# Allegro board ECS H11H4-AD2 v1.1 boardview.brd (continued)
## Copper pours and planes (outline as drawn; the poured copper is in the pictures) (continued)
GND on PWR (solid shape): outline of 10788 points within 117.45,130.68 192.89,199.01
GND on PWR (solid shape): outline of 19119 points within 73.76,77.22 183.87,203.58
GND on GND (solid shape): outline of 132067 points within 0.51,0.51 199.49,243.33
+ATX_3VSB on TOP (solid shape): 165.79,58.24 165.79,54.03 165.38,53.62 162.17,53.62 161.86,53.51 161.72,53.21 161.72,53.19 161.67,53.14 161.67,52.2 161.34,51.87 159.31,51.87 159.27,51.88 159.26,51.92 159.26,53.42 159.26,53.57 159.11,53.72 159.11,55.63 158.6,56.13 155.63,56.13 155.59,56.15 155.58,56.18 155.58,56.36 154.15,57.78 154.15,58.4 154.53,58.78 165.25,58.78
+ATX_3VSB on BOTTOM (solid shape): outline of 112 points within 29.29,48.98 57.76,57
+ATX_5VSB on TOP (solid shape): 6.88,154.94 6.92,154.93 6.93,154.89 6.93,153.33 7.49,153.33 7.49,154.89 7.51,154.93 7.54,154.94 10.13,154.94 10.52,154.56 10.52,153.29 9.75,152.53 9.75,150.75 9.63,150.62 9.25,150.62 8.61,151.26 5.82,151.26 5.56,151.51 5.56,152.53 6.2,153.16 6.2,153.31 6.22,153.33 6.22,154.89 6.24,154.93 6.27,154.94
+ATX_5VSB on TOP (solid shape): outline of 127 points within 146.66,42.55 165.67,51.69
+DDR_VTT on TOP (solid shape): 56.49,88.29 56.49,87.73 56.16,87.4 56.16,84.96 56.47,84.65 56.47,84.25 56.47,83.86 56.16,83.54 56.16,81.14 57.16,80.14 59.53,80.14 60.32,80.92 95.91,80.92 96.06,80.77 96.06,79.81 95.91,79.65 60.84,79.65 60.05,78.87 56.63,78.87 54.89,80.61 54.89,88.57 55.02,88.7 56.08,88.7
+DDR_VTT on TOP (solid shape): 144.69,70.15 144.73,70.14 144.74,70.1 144.74,69.92 144.85,69.81 144.86,69.79 144.86,69.77 145.41,69.28 145.61,69.99 145.59,70.09 145.69,70.15 145.93,70.15 146,70.08 146.01,70.06 146.01,70.03 146.4,69.42 146.81,70.01 146.81,70.11 146.9,70.15 148.23,70.15 149.02,69.37 149.02,67.69 148.77,67.44 145.62,67.44 145.31,67.74 145.31,68.33 144.5,69.14 144.5,70.1 144.55,70.15
+DDR_VTT on BOTTOM (solid shape): 121.01,70.89 141.74,70.89 143.39,69.24 146.65,69.24 147.56,70.15 148.11,70.15 148.64,69.62 148.64,68.96 147.65,67.97 142.87,67.97 141.21,69.62 120.24,69.62 110.21,79.65 94.82,79.65 94.64,79.83 94.64,80.8 94.77,80.92 95.35,80.92 95.4,80.92 110.97,80.92
+DRIVER_POWER on TOP (solid shape): 197.87,130.1 197.87,126.82 197.61,126.57 194.97,126.57 194.82,126.72 194.82,128.32 194.41,128.73 191.47,128.73 191.36,128.83 191.36,130.23 191.49,130.35 197.61,130.35
+DVI_VGA_VCC on TOP (solid shape): 164.01,232.89 164.01,231.9 164.31,231.6 164.31,231.53 164.3,231.5 164.26,231.48 163.92,231.48 163.79,231.36 163.23,231.36 161.42,229.54 161.42,227.53 161.01,227.13 157,227.13 156.82,227.3 156.82,229.26 160.78,233.22 163.68,233.22
+R_VDD10 on TOP (solid shape): 58.84,195.8 58.84,194.98 58.85,194.97 58.85,194.74 60.2,193.4 60.2,192.61 59.99,192.41 55.73,192.41 55.58,192.56 55.58,195.81 55.83,196.06 58.57,196.06
+R_VDD33 on TOP (solid shape): 55.3,193.22 55.3,191.13 57,189.43 57,186.74 55.93,185.67 55.02,185.67 54.74,185.95 54.74,190.4 54.51,190.63 53.92,190.63 53.7,190.86 53.7,192.32 53.7,192.51 53.72,192.53 53.72,193.29 53.9,193.47 55.04,193.47
+R_VDDREG on TOP (solid shape): 52.86,199.87 52.86,199.24 53.42,198.68 53.42,198.15 53.68,197.88 53.68,193.7 53.42,193.43 53.42,192.48 53.21,192.28 52.25,192.28 52.02,192.51 52.02,195.84 52.03,195.88 52.07,195.89 52.48,196.32 52.07,196.75 52.03,196.77 52.02,196.81 52.02,197.87 52.68,198.53 52.68,199.87 52.73,199.92 52.81,199.92
+USB3VCC2_2 on TOP (solid shape): outline of 92 points within 4.29,47.57 10.64,63.63
+USB3VCC_C1 on TOP (solid shape): 107.65,233.68 110.67,233.68 111.38,232.97 111.38,224.69 111,224.31 107.98,224.31 105.16,221.49 105.16,220.57 106.58,219.15 107.37,219.15 108.43,218.08 108.43,218.06 109.63,216.87 109.63,214 109.35,213.72 107.67,213.72 107.44,213.94 107.44,213.97 107.34,214.07 107.34,214.91 102.21,220.04 102.21,222.53 106.58,226.9 107.65,226.9 109.7,228.96 109.7,230.66 109.09,231.27 107.09,231.27 106.26,232.09 106.26,232.1 106.12,232.31 105.91,232.45 105.9,232.45 105.87,232.49 105.65,232.5 105.51,232.49 104.17,232.49 103.99,232.66 103.99,234.26 104.52,234.8 106.53,234.8
+USB3VCC_C1 on BOTTOM (solid shape): outline of 255 points within 104.57,225.35 111.35,234.42
+USBVCC0 on TOP (solid shape): outline of 213 points within 76.95,202.41 86.97,233.05
+USBVCC1 on TOP (solid shape): 16.69,27.53 16.9,27.53 16.91,27.5 17.28,27.2 17.7,27.42 17.7,27.43 17.75,27.46 18.44,27.46 18.77,27.13 20.14,27.13 20.24,27.03 20.24,25.83 15.62,25.83 15.61,25.84 13.55,25.84 12.41,24.7 12.3,24.7 12.29,24.69 10.03,24.69 9.93,24.67 9.85,24.61 4.04,24.61 3.76,24.89 3.76,27.71 4.17,28.12 8.43,28.12 9.19,28.88 12.16,28.88 12.17,28.83 12.68,28.46 13.01,29 13,29.03 13.16,29.18 15.04,29.18
+USBVCC2 on TOP (solid shape): 15.77,77.95 15.77,76.1 15.58,75.91 6.41,75.91 5.69,75.18 4.29,75.18 4.04,75.44 4.04,78.61 4.29,78.87 14.86,78.87
+V_3P3_LAN on TOP (solid shape): 10.64,161.93 10.64,159.38 10.39,159.13 8.99,159.13 8.61,158.75 7.54,158.75 7.51,158.76 7.49,158.8 7.49,160.36 6.93,160.36 6.93,158.8 6.92,158.76 6.88,158.75 6.32,158.75 6.22,158.85 6.22,160.36 6.2,160.38 6.2,161.93 6.45,162.18 10.39,162.18
+VCORE on TOP (solid shape): outline of 3941 points within 115.21,139.19 178.41,189.36
+VCORE on BOTTOM (solid shape): outline of 146 points within 156.64,165.96 176.83,178.82
+VCORE on BOTTOM (solid shape): outline of 2169 points within 120.8,142.01 147.42,189.36
+VCORE on PWR (solid shape): 159.61,168.2 159.61,166.02 159.33,165.74 153.23,165.74 152.37,164.87 152.25,164.85 152.2,164.96 147.89,168.36 147.71,162.88 147.76,162.76 147.66,162.69 146.13,162.69 146.09,162.7 146.08,162.74 146.08,164.16 143.2,167.03 141.12,167.03 140.49,167.66 140.49,170.97 141.98,172.47 155.35,172.47
+VDIMM on TOP (solid shape): outline of 1251 points within 109.32,76.07 130.78,88.39
+VDIMM on BOTTOM (solid shape): 130.78,79.5 130.78,78.1 128.75,76.07 124.43,76.07 123.93,76.58 123.93,79.38 124.31,79.76 130.53,79.76
+VDIMM on PWR (solid shape): outline of 6142 points within 95.12,76.07 164.24,133.65
+VGA_VCC on TOP (solid shape): 166.88,235.94 166.88,233.81 166.83,233.76 166.37,233.76 166.19,233.93 165.71,233.93 165.38,233.6 162.61,233.6 162.43,233.78 162.43,234.67 163.93,236.17 166.65,236.17
+VGA_VCC on BOTTOM (solid shape): outline of 726 points within 164.8,234.92 182.85,242.6
AUGND on TOP (solid shape): outline of 259 points within 31.67,229.18 40.67,238.18
AUGND on PWR (solid shape): outline of 3950 points within 0.51,192.15 61.82,243.33
AUGND on GND (solid shape): outline of 3922 points within 0.51,192.15 61.82,243.33
BZ_P on TOP (solid shape): 191.29,35.71 191.29,30.11 191.27,30.08 191.24,30.06 190.42,30.06 190.42,29.87 191.24,29.87 191.27,29.85 191.29,29.82 191.29,29.61 191.27,29.58 191.24,29.56 190.42,29.56 190.42,29.37 191.24,29.37 191.27,29.35 191.29,29.32 191.29,29.11 191.27,29.08 191.24,29.06 190.42,29.06 190.42,28.87 191.24,28.87 191.27,28.85 191.29,28.82 191.29,28.09 191.06,27.86 188.26,27.86 188.04,28.09 188.04,29.29 188.19,29.44 188.87,29.44 189.13,29.69 189.13,30.59 189.14,30.62 189.16,30.64 189.43,31.04 189.16,31.44 189.14,31.46 189.13,31.49 189.13,31.85 186.41,34.57 186.41,37.92 186.77,38.28 188.72,38.28
Net_179 on TOP (solid shape): outline of 251 points within 81.19,106.01 89.32,114.14
Net_913 on BOTTOM (solid shape): outline of 251 points within 81.19,106.01 89.32,114.14
Net_918 on TOP (solid shape): outline of 250 points within 81.19,181.01 89.32,189.14
Net_918 on BOTTOM (solid shape): outline of 250 points within 81.19,181.01 89.32,189.14
Net_1017 on TOP (solid shape): outline of 251 points within 156.2,106.01 164.33,114.14
Net_1017 on BOTTOM (solid shape): outline of 251 points within 156.2,106.01 164.33,114.14
Net_1022 on TOP (solid shape): outline of 251 points within 156.2,181.01 164.33,189.14
Net_1022 on BOTTOM (solid shape): outline of 251 points within 156.2,181.01 164.33,189.14
P95_PH on TOP (solid shape): 117.07,56.95 117.07,55.14 117.17,55.04 118.34,55.04 118.47,55.17 119.94,55.17 120.12,54.99 120.12,52.78 120.14,52.78 120.37,52.55 120.37,51.16 120.04,50.83 119.41,50.83 118.72,50.14 112.83,50.14 111.96,49.28 109.3,49.28 108.43,48.41 108.43,47.4 108.28,47.24 107.57,47.24 106.77,48.04 106.77,56.27 107.47,56.97 117.04,56.97
P95_PH on BOTTOM (solid shape): 117.07,56.95 117.07,55.14 117.17,55.04 118.34,55.04 118.47,55.17 119.94,55.17 120.12,54.99 120.12,52.78 120.14,52.78 120.37,52.55 120.37,51.16 120.04,50.83 119.41,50.83 118.72,50.14 112.83,50.14 111.96,49.28 109.3,49.28 108.43,48.41 108.43,47.4 108.28,47.24 107.57,47.24 106.77,48.04 106.77,56.27 107.47,56.97 117.04,56.97
P95_PH on PWR (solid shape): 120.12,56.36 120.12,52.8 120.37,52.55 120.37,51.21 120.09,50.93 119.32,50.93 118.54,50.14 112.82,50.14 111.96,49.28 109.29,49.28 108.43,48.42 108.43,47.4 108.27,47.24 107.57,47.24 106.78,48.04 106.78,56.79 107.01,57.02 119.45,57.02
PHASE1_A on TOP (solid shape): 125.7,198.75 125.7,195.96 127.23,194.44 127.23,191.64 127.1,191.52 126.85,191.52 125.7,192.66 125.45,192.66 124.69,191.9 124.69,190.25 124.56,190.12 123.47,190.12 120.88,187.53 120.88,183.64 120.62,183.39 116.31,183.39 115.93,183.77 115.93,188.59 116.94,189.61 116.94,190.88 115.93,191.9 115.93,196.85 116.05,196.98 119.86,196.98 121.89,199.01 125.45,199.01
PHASE1_A on BOTTOM (solid shape): 125.7,198.88 125.7,196.09 127.23,194.56 127.23,190.37 126.97,190.12 123.44,190.12 120.88,187.55 120.88,183.64 120.62,183.39 116.31,183.39 115.93,183.77 115.93,188.59 116.94,189.61 116.94,190.88 115.93,191.9 115.93,196.85 116.05,196.98 119.86,196.98 121.89,199.01 125.58,199.01
PHASE1_A on PWR (solid shape): 125.7,198.85 125.7,196.06 127.23,194.53 127.23,191.64 127.1,191.52 126.85,191.52 125.7,192.66 125.45,192.66 124.69,191.9 124.69,190.25 124.56,190.12 123.51,190.12 120.88,187.48 120.88,183.67 120.59,183.39 116.26,183.39 115.93,183.72 115.93,188.56 116.94,189.58 116.94,190.91 115.93,191.93 115.93,196.82 116.08,196.98 119.89,196.98 121.93,199.01 125.55,199.01
PHASE1_B on TOP (solid shape): 178.54,160.4 180.06,160.4 180.95,161.29 185.78,161.29 185.9,161.16 185.9,156.97 187.55,155.32 187.55,152.27 187.43,152.15 187.22,152.15 187.21,152.15 186.85,152.21 186.49,152.15 185.39,152.15 184.76,151.51 184.76,149.68 184.45,149.38 179.86,149.38 179.35,149.89 179.35,150.42 179.55,150.62 180.7,150.62 181.84,151.76 181.84,152.4 181.46,152.78 181.46,153.03 181.25,153.24 179.91,153.24 176.81,156.34 172.82,156.34 172.57,156.59 172.57,161.16 172.69,161.29 177.65,161.29
PHASE1_B on BOTTOM (solid shape): 178.54,160.4 180.06,160.4 180.95,161.29 185.78,161.29 185.9,161.16 185.9,156.97 187.55,155.32 187.55,152.27 187.43,152.15 185.39,152.15 184.76,151.51 184.76,149.68 184.43,149.35 179.86,149.35 179.3,149.91 179.3,153.85 176.81,156.34 172.82,156.34 172.57,156.59 172.57,161.16 172.69,161.29 177.65,161.29
PHASE1_B on PWR (solid shape): 178.51,160.4 180.09,160.4 180.98,161.29 185.74,161.29 185.9,161.13 185.9,156.94 187.55,155.29 187.55,152.3 187.4,152.15 185.36,152.15 184.76,151.54 184.76,149.64 184.47,149.35 179.96,149.35 179.3,150.02 179.3,150.11 179.81,150.62 180.7,150.62 181.84,151.76 181.84,152.4 181.46,152.78 181.46,153.03 181.27,153.23 179.92,153.23 177.57,155.57 177.57,155.57 176.82,156.34 172.85,156.34 172.57,156.62 172.57,161.13 172.73,161.29 177.62,161.29
PHASE2_A on TOP (solid shape): 141.45,198.88 141.45,196.22 144.75,192.91 144.75,191.52 144.63,191.39 144.5,191.39 143.1,192.79 142.85,192.79 142.6,192.53 142.6,190.37 142.34,190.12 142.21,190.12 139.04,186.94 139.04,183.77 138.66,183.39 133.83,183.39 133.71,183.51 133.71,188.72 134.59,189.61 134.59,191.01 133.71,191.9 133.71,198.88 133.83,199.01 141.33,199.01
PHASE2_A on BOTTOM (solid shape): 141.45,198.88 141.45,196.22 144.75,192.91 144.75,190.37 144.5,190.12 142.21,190.12 139.04,186.94 139.04,183.77 138.66,183.39 133.83,183.39 133.71,183.51 133.71,188.72 134.59,189.61 134.59,190.88 133.71,191.77 133.71,198.88 133.83,199.01 141.33,199.01
PHASE2_A on PWR (solid shape): 141.45,198.85 141.45,196.18 144.75,192.88 144.75,191.52 144.63,191.39 144.5,191.39 143.1,192.79 142.85,192.79 142.6,192.53 142.6,190.5 142.21,190.12 142.21,190.12 139.04,186.95 139.04,183.8 138.63,183.39 133.86,183.39 133.71,183.55 133.71,188.69 134.59,189.58 134.59,190.91 133.71,191.8 133.71,198.85 133.86,199.01 141.29,199.01
PHASE2_B on TOP (solid shape): 178.66,142.88 179.93,142.88 180.82,143.76 186.03,143.76 187.55,142.24 187.55,134.75 187.43,134.62 187.22,134.62 187.21,134.62 186.85,134.68 186.49,134.62 185.27,134.62 183.36,132.72 180.82,132.72 180.7,132.84 180.7,133.35 181.97,134.62 181.97,134.87 181.71,135.13 179.73,135.13 176.17,138.68 172.69,138.68 172.57,138.81 172.57,143.64 172.69,143.76 177.77,143.76
PHASE2_B on BOTTOM (solid shape): 178.66,142.88 179.93,142.88 180.82,143.76 186.03,143.76 187.55,142.24 187.55,134.75 187.43,134.62 185.27,134.62 183.36,132.72 180.44,132.72 180.31,132.84 180.31,134.54 176.17,138.68 172.69,138.68 172.57,138.81 172.57,143.64 172.69,143.76 177.77,143.76
PHASE2_B on PWR (solid shape): 178.63,142.88 179.96,142.88 180.85,143.76 186,143.76 187.55,142.21 187.55,134.78 187.4,134.62 185.24,134.62 183.33,132.72 179.46,132.72 179.38,132.8 179.36,132.83 179.38,132.87 179.39,132.88 179.41,132.88 179.76,133.34 179.29,133.69 179.21,133.71 179.17,133.79 179.17,135.69 176.18,138.68 172.73,138.68 172.57,138.84 172.57,143.51 172.56,143.51 172.55,143.54 172.54,143.57 172.56,143.6 172.73,143.76 177.74,143.76
PHASE3_A on TOP (solid shape): 178.41,178.31 179.93,178.31 180.82,179.2 185.78,179.2 185.9,179.07 185.9,174.88 187.55,173.23 187.55,170.18 187.43,170.05 184.76,170.05 184.12,169.42 184.12,165.99 183.87,165.74 179.43,165.74 179.17,165.99 179.17,167.26 181.46,169.55 181.46,171.2 180.61,172.05 179.24,172.05 177.04,174.24 172.69,174.24 172.57,174.37 172.57,179.07 172.69,179.2 177.52,179.2
PHASE3_A on BOTTOM (solid shape): 178.41,178.31 179.93,178.31 180.82,179.2 185.78,179.2 185.9,179.07 185.9,174.88 187.55,173.23 187.55,170.18 187.43,170.05 184.76,170.05 184.12,169.42 184.12,165.99 183.87,165.74 180.7,165.74 180.16,166.27 180.16,171.09 177.01,174.24 172.69,174.24 172.57,174.37 172.57,179.07 172.69,179.2 177.52,179.2
PHASE3_A on PWR (solid shape): 178.38,178.31 179.96,178.31 180.85,179.2 185.74,179.2 185.9,179.04 185.9,174.85 187.55,173.2 187.55,170.21 187.4,170.05 184.73,170.05 184.12,169.45 184.12,166.02 183.84,165.74 179.46,165.74 179.17,166.02 179.17,167.26 181.46,169.55 181.46,171.2 180.64,172.01 179.27,172.01 179.17,172.11 179.17,172.12 177.04,174.24 172.73,174.24 172.57,174.4 172.57,179.04 172.73,179.2 177.49,179.2
R_REGOUT on TOP (solid shape): 53.4,199.73 54.29,199.73 54.79,199.24 58.34,199.24 58.57,199.01 58.57,197.03 58.45,196.9 55.04,196.9 53.64,198.3 53.64,198.78 53.09,199.34 53.09,199.87 53.14,199.92 53.21,199.92
SIO_GND on TOP (solid shape): 124.4,35.79 124.66,35.79 124.78,35.66 124.78,35.28 124.35,34.85 123.43,34.85 123.27,35 123.27,35.83 123.48,36.03 124.15,36.03
SIO_GND on GND (solid shape): 127.74,41.28 127.74,37.86 127.73,37.84 127.57,37.68 127.51,37.49 127.51,37.47 125.22,35.18 123.52,35.18 122.13,36.58 120.77,36.58 119.38,35.18 116.92,35.18 115.42,36.68 115.42,41.1 115.45,41.17 115.51,41.21 115.9,41.61 115.51,42.02 115.45,42.05 115.42,42.12 115.42,42.44 115.9,42.93 121.36,42.93 122.3,43.87 122.42,43.89 122.48,43.79 122.96,43.39 123.27,43.93 123.28,44.03 123.36,44.07 124.94,44.07
SYS_FAN_P2 on TOP (solid shape): 180.21,70.05 180.21,66.55 183.24,63.53 183.24,54.94 183.97,54.2 186.26,54.2 186.61,53.85 186.61,52.12 186.26,51.77 182.78,51.77 179.91,54.64 178.84,54.64 178.74,54.74 178.74,55.35 180.76,57.37 180.76,62.38 177.8,65.34 177.8,68.33 178.36,68.88 178.36,70.13 178.56,70.33 179.93,70.33
VSA_PH on TOP (solid shape): 104.75,200.15 108.56,200.15 108.69,200.03 108.69,192.25 109.83,191.11 109.83,188.49 109.25,187.91 103.15,187.91 102.46,188.59 102.46,197.99 103.35,198.88 103.35,200.23 103.71,200.58 104.32,200.58
VSA_PH on BOTTOM (solid shape): 108.69,199.72 108.69,192.25 109.83,191.11 109.83,188.49 109.25,187.91 103.39,187.91 102.44,188.86 102.44,197.97 103.35,198.88 103.35,199.9 103.58,200.13 108.28,200.13
VSA_PH on PWR (solid shape): 104.74,200.13 108.27,200.13 108.69,199.71 108.69,192.25 109.83,191.1 109.83,188.5 109.24,187.91 103.15,187.91 102.34,188.73 102.34,190.98 102.44,191.08 102.44,197.96 103.35,198.88 103.35,200.22 103.71,200.58 104.29,200.58
N17804048 on TOP (solid shape): 165.33,230.71 165.33,230.69 165.34,230.59 165.38,230.5 165.38,227.55 165.87,227.07 165.88,227.03 165.87,226.99 165.71,226.84 165.69,226.83 165.67,226.82 165.35,226.7 165.23,226.37 165.22,226.35 165.21,226.34 163.65,224.78 159.93,224.78 159.69,225.02 159.69,226.26 160.05,226.62 161.26,226.62 161.95,227.3 161.95,229.26 163.42,230.73 165.3,230.73
N18832986 on TOP (solid shape): 195.55,30.86 195.55,28.78 195.17,28.4 191.67,28.4 191.62,28.45 191.62,30.99 191.87,31.24 195.17,31.24
N20949106 on TOP (solid shape): 169.27,31.5 169.27,27.94 169.01,27.69 165.07,27.69 165,27.76 165,31.67 165.07,31.75 169.01,31.75
N23257447 on TOP (solid shape): 142.14,74.8 145.77,74.8 145.77,73.15 142.93,73.15 142.7,73.38 137.95,73.38 136.17,71.6 133.63,71.6 133.15,72.09 133.15,74.68 134.95,76.48 140.46,76.48
N23257447 on BOTTOM (solid shape): 142.14,74.8 145.72,74.8 145.76,74.79 145.77,74.75 145.77,73.2 145.76,73.17 145.72,73.15 142.93,73.15 142.7,73.38 137.95,73.38 136.17,71.6 133.63,71.6 133.15,72.09 133.15,74.68 134.95,76.48 140.46,76.48
N23257447 on PWR (solid shape): 142.24,74.8 145.72,74.8 145.77,74.75 145.77,73.33 145.59,73.15 143.03,73.15 142.78,73.41 141.81,73.41 141.68,73.53 138.17,73.53 136.14,71.5 133.68,71.5 133.2,71.99 133.2,74.7 134.95,76.45 140.59,76.45
N23257703 on TOP (solid shape): 148.97,78.66 148.97,77.88 146.08,74.98 145.67,74.98 145.67,77.09 146.28,77.7 146.66,77.7 147.85,78.89 148.74,78.89
N23749919 on TOP (solid shape): 64.62,133.25 64.62,129.77 62.84,127.99 62.84,126.9 63.09,126.64 63.09,123.93 62.97,123.8 62.15,123.8 62.08,123.88 62.08,124.74 61.54,125.27 60.86,125.27 60.2,125.93 59.51,125.93 59.26,126.19 59.26,127 60.81,128.55 60.81,132.46 61.7,133.35 64.52,133.35
N23749919 on PWR (solid shape): 64.62,133.24 64.62,129.77 62.84,127.99 62.84,126.89 62.99,126.75 63.04,126.75 63.08,126.73 63.09,126.7 63.09,124 62.91,123.83 62.13,123.83 62.08,123.88 62.08,124.77 61.5,125.35 60.86,125.35 60.23,125.98 60.15,125.98 60.02,126.11 59.39,126.11 59.28,126.22 59.28,127.02 60.81,128.55 60.81,132.48 61.67,133.35 64.51,133.35
N23750037 on TOP (solid shape): 62.2,123.29 62.2,121.84 62.43,121.62 62.43,117.77 61.29,116.62 61.26,116.62 60.79,116.15 59.94,116.15 59.79,116 57.94,116 57.7,116.24 57.7,116.65 57.68,116.66 57.68,118.01 57.7,118.04 57.73,118.06 58.03,118.06 58.05,118.05 58.21,117.9 58.39,117.86 58.46,117.86 58.76,118.01 58.82,118.34 58.82,118.36 58.83,118.39 59.44,119 59.46,119 59.75,119.21 59.75,119.56 59.75,119.66 59.84,119.71 60.01,119.71 60.18,119.53 60.19,119.53 60.62,119.33 60.91,119.7 60.91,119.76 60.9,119.85 60.87,119.93 60.86,119.94 60.87,119.97 61.06,120.17 61.06,121.13 61.32,121.39 61.32,122.91 61.77,123.37 61.77,123.44 61.85,123.52 61.98,123.52
N24048876 on TOP (solid shape): 158.6,220.73 158.6,217.17 158.22,216.79 157.33,216.79 157.07,217.04 157.07,220.85 157.2,220.98 158.34,220.98
N24053069 on TOP (solid shape): 194.54,128.09 194.54,119.1 194.26,118.82 193.17,118.82 192.38,119.61 192.38,128.17 192.56,128.35 194.28,128.35
N24053944 on TOP (solid shape): 190.35,180.21 190.73,180.21 190.76,180.18 190.8,180.11 190.84,180.05 190.85,180.03 190.86,180.01 190.86,179.7 190.73,179.58 190.35,179.58 190.09,179.32 190.09,178.56 189.97,178.44 189.46,178.44 189.33,178.56 189.33,179.2 188.57,179.96 188.57,180.85 188.82,181.1 189.46,181.1
N24062859 on TOP (solid shape): 191.74,144.78 192.13,144.78 192.25,144.65 192.25,144.27 192.13,144.15 191.74,144.15 191.49,143.89 191.49,143.13 191.36,143 190.86,143 190.73,143.13 190.73,143.76 189.97,144.53 189.97,145.42 190.22,145.67 190.86,145.67

Small or netless copper shapes (teardrops, artwork), in the pictures only: 10 on TOP, 6 on BOTTOM, 1 on PWR, 1 on GND

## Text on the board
Ref Des/Silkscreen Top: A | N | T | H11H4-AD2 | 15-KH9-011100 | B | R | V:1.1 | F | Q | P | O | I | G | J | K | X | U | S | V | L | H | M | D | E | C
User.14: 15-KH9-011100 | H11H4-AD2 V:1.1 TOP
User.15: 15-KH9-011100 | H11H4-AD2 V:1.1 BOTTOM
User.23: 2 | 10 | 7 | 48 | B82 | B81 | A81 | A82 | AUDIO | USB(2.0)*2 | RJ-45 | USB(3.0)*2 | DP | HDMI | VGA | 12 | 11 | 8 | AY | A | 1 | 40 | 6 | 15 | 5 | 64 | 24 | 13 | 16 | 20 | 42 | 75 | 21 | 74 | 120 | 240 | 121 | 33 | 32 | 22 | 23 | B2 | B1 | A1 | A2 | B18 | B17 | A17 | A18 | + | ELITEGROUP COMPUTER SYSTEM | Issue Data | Model No. | 2014/02/27 | Q87H3-AD2 | Rev. | SILK_TOP | 1.0
User.43: 59.1
User.45: +VCCIO | GND | N23749919 | VSA_PH | +V1P0A | +1V05_SA | P95_PH | +VIN_SA | n23257447 | +VIN_CPU | PHASE2_B | PHASE3_A | PHASE1_B | +12V_4P | PHASE1_A | PHASE2_A | FIGURE | SIZE | 10.0 | 12.0 | 14.0 | 20.0 | 26.0 | 28.0 | 30.0 | 32.0 | 33.0 | 36.0 | 37.0 | 40.0 | 42.0 | 44.0 | 48.0 | 54.0 | 55.0 | 56.0 | 60.0 | 72.0 | 76.0 | 92.0 | 128.0 | 165.0 | 64.0 | 93.0 | 97.0 | 124.0 | 152.0 | 160.0 | 44.0x40.0 | 47.0x32.0 | 64.0x36.0 | 78.0x60.0 | 90.0x72.0 | 94.0x76.0 | 108.0x36.0 | 96.0x72.0 | DRILL CHART: TOP to BOTTOM | ALL UNITS ARE IN MILS | TOLERANCE | +3.0/-3.0 | +4.0/-4.0 | PLATED | NON-PLATED | QTY | 628 | 3628 | 64 | 31 | 2 | 698 | 14 | 21 | 16 | 8 | 147 | 15 | 1 | 6 | 4 | 24 | 5 | 3 | 10 | 13 | +5VSB | AUGND | +12V | +VCC3 | +3VSB | +VCC | +VDIMM
